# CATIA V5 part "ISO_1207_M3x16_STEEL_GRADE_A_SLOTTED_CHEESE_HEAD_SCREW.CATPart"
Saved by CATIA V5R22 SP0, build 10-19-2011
Part number: ISO 1207 SCREW M3x16 STEEL GRADE A SLOTTED CHEESE HEAD
Publications: "Mating Face", "Axis"
Bounding box of the stored display mesh (mm): x -18 to 0, y -2.741 to 2.741, z -2.75 to 2.75
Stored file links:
  D:\PER\CAO_PER_MODIF_2025\CAO_PER_pick&place_2024P\Cadre\ISO_1207_M3x16_STEEL_GRADE_A_SLOTTED_CHEESE_HEAD_SCREW.CATPart
  C:\Program Files\Dassault Systemes\B22\win_b64\startup\components\MechanicalStandardParts\EN_Standards\Design_Tables\EN_ISO_1207_GRADE_A_SLOTTED_CHEESE_HEAD_SCREW.txt
  C:\Program Files\Dassault Systemes\B22\win_b64\startup\components\MechanicalStandardParts\ISO_Standards\Design_Tables\ISO_1207_GRADE_A_SLOTTED_CHEESE_HEAD_SCREW.txt
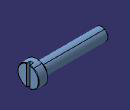
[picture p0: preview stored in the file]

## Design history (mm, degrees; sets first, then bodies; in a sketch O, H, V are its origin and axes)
Parameters
  d_dia = 3 mm
  dk_nom_head_dia = 5.5 mm
  k_max_head_depth = 2 mm
  n_nom_Slot_Width = 0.8 mm
  t_min_Slot_Depth = 0.85 mm
  r_min = 0.1 mm
  p_pitch = 0.5 mm
  Threading = 15 mm
  l_Length_nom = 16 mm
Body1 "PartBody" (main body)
  Sketch1 on zx-plane, origin (0, 0, 0), H (-1, 0, 0), V (0, 0, 1)
    line L1 (0, 0) -> (0, 2.575)
    line L2 (0, 2.575) -> (2, 2.75)
    point P2 (2, 2.75)
    line L3 (2, 2.75) -> (2, 1.4375)
    axis line L4 (-15.2845, 0) -> (155.0819, 0)
    reference intersected line E1 through (1000000, 0) direction (-1, 0) from xy-plane
    line L5 (2, 1.4375) -> (2.5, 1.4375)
    point P5 (3, 1.5)
    line L6 (3, 1.5) -> (18, 1.5)
    point P6 (18, 1.5)
    line L7 (18, 1.5) -> (18, 0)
    point P7 (18, 0)
    line L8 (3, 1.5) -> (2.5, 1.4375)
    point P9 (2.5, 1.4375)
    distance L1 P2 = 2 {= k_max_head_depth}
    distance P2 L4 = 2.75 {= dk_nom_head_dia /2}
    angle L4 L2 = 175
    length L7 = 1.5 {= d_dia /2}
    distance L5 L4 = 1.4375 {= (d_dia -(p_pitch/4))/2}
    distance P6 P5 = 15 {= Threading}
    distance L7 L1 = 18 {= l_Length_nom +k_max_head_depth}
    distance P9 P5 H = 0.5 {= p_pitch}
    vertical: L1 V, L3 V, L7 V
    horizontal: L4 H, L5 H
    coincidence: L4 E1, P7 L4
    parallelism: L6 L5
  Shaft1: profile Sketch1, axis Sketch1.L4, angle 360
  Fillet1: radius 0.1 {= r_min}, on edge [face of Shaft1 | face of Shaft1]
  Sketch2 on xy-plane, origin (0, 0, 0), H (1, 0, 0), V (0, 1, 0)
    line L1 (0, 0.4) -> (-0.85, 0.4)
    line L2 (-0.85, 0.4) -> (-0.85, -0.4)
    line L3 (-0.85, -0.4) -> (0, -0.4)
    line L4 (0, -0.4) -> (0, 0.4)
    distance O L2 = 0.85 {= t_min_Slot_Depth}
    distance H L1 = 0.4 {= n_nom_Slot_Width /2}
    distance H L3 = 0.4 {= n_nom_Slot_Width /2}
    vertical: L2 V
    coincidence: L4 V
  Pocket1: profile Sketch2, direction (0, 0, -1), through (limit type 3), opposite side length 20
  Fillet2: radius 0.1 {= r_min}, on edge [face of Shaft1 | face of Shaft1]
  Thread1: diameter 3 {= d_dia}, depth 15 {= Threading}, pitch 1, on face of Shaft1, from face of Shaft1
